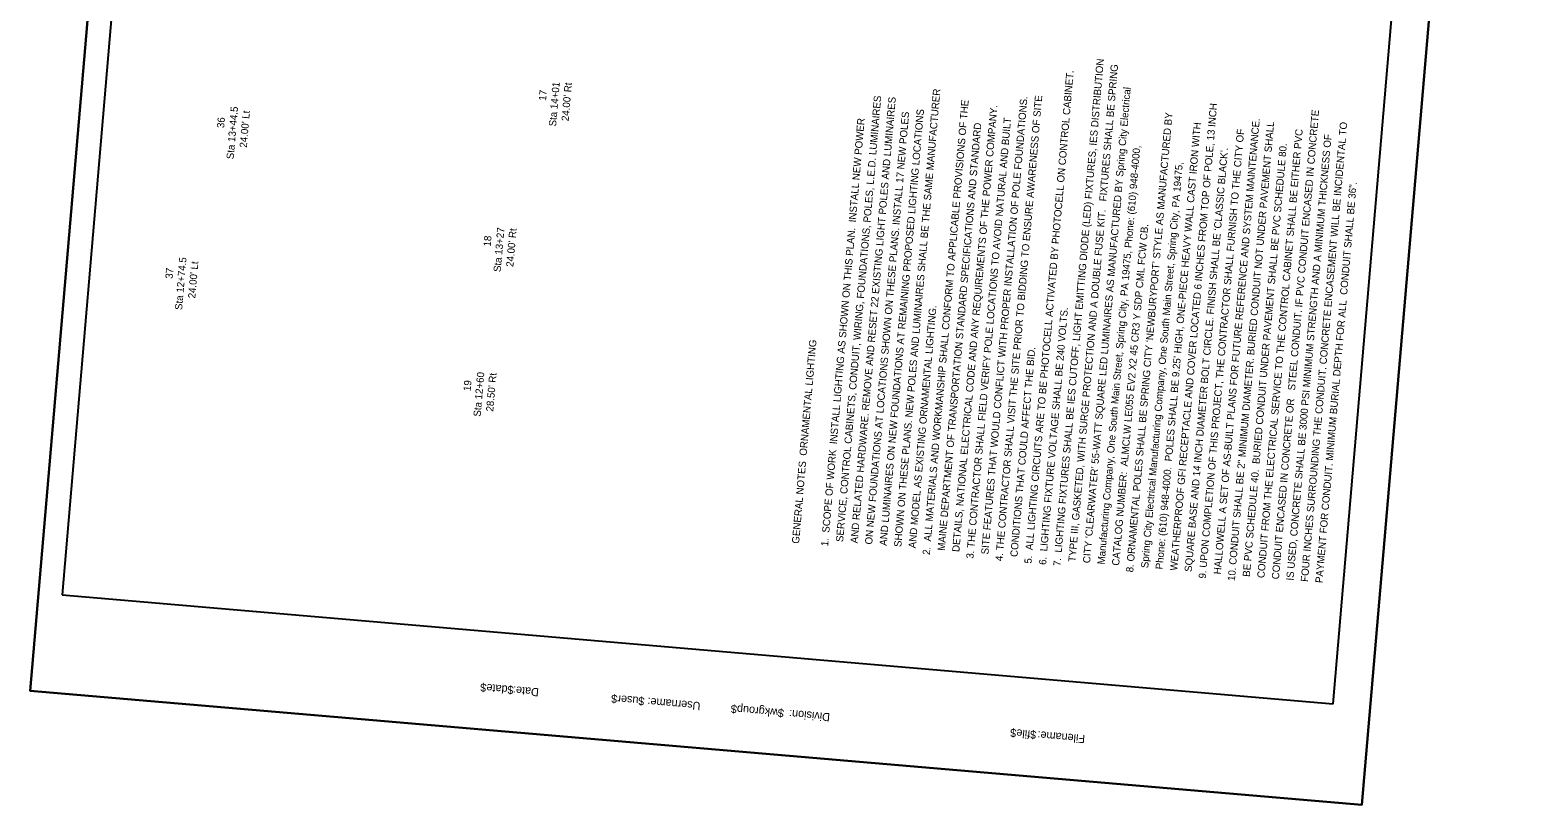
# Model space of a CAD drawing. Extents: x 1137099 to 1137719, y 529062 to 529956.
# Drawn here: x 1137099 to 1137719, y 529062 to 529381 of the extents above; entities that cross this region are included whole.
import ezdxf

# ---------------------------------------------------------------- set-up
doc = ezdxf.new("R2010")
doc.units = 0
for name, color, linetype in [('ANNOTATION', 7, 'Continuous'), ('BORDER', 7, 'Continuous'), ('D_Lighting_Text', 7, 'Continuous'), ('PLOT BOUNDARY', 7, 'Continuous')]:
    doc.layers.add(name, color=color, linetype=linetype)

msp = doc.modelspace()

# ---------------------------------------------------------------- linework, layer by layer
at = {"layer": 'ANNOTATION'}
msp.add_lwpolyline([(1137098.65, 529108.8), (1137171.14, 529955.71), (1137719.13, 529908.81), (1137646.65, 529061.9)], close=True, dxfattribs=at)
at = {"layer": 'BORDER'}
for p, q in [((1137179.99, 529945.38), (1137111.77, 529148.3)), ((1137634.86, 529103.53), (1137703.08, 529900.61)), ((1137111.77, 529148.3), (1137634.86, 529103.53))]:
    msp.add_line(p, q, dxfattribs=at)
at = {"layer": 'PLOT BOUNDARY'}
msp.add_lwpolyline([(1137646.65, 529061.9), (1137719.13, 529908.81), (1137171.14, 529955.71), (1137098.65, 529108.8)], close=True, dxfattribs=at)

# ---------------------------------------------------------------- texts
at = {"layer": 'ANNOTATION'}
for s, p in [('7.  LIGHTING FIXTURES SHALL BE IES CUTOFF, LIGHT EMITTING DIODE (LED) FIXTURES, IES DISTRIBUTION ', (1137522.7, 529160.05)), ('5.  ALL LIGHTING CIRCUITS ARE TO BE PHOTOCELL ACTIVATED BY PHOTOCELL ON CONTROL CABINET.', (1137510.75, 529161.07)), ('  TYPE III, GASKETED, WITH SURGE PROTECTION AND A DOUBLE FUSE KIT.   FIXTURES SHALL BE SPRING ', (1137528.68, 529159.54)), ('  SHOWN ON THESE PLANS. NEW POLES AND LUMINAIRES SHALL BE THE SAME MANUFACTURER ', (1137456.95, 529165.68)), ('  CITY ‘CLEARWATER’ 55-WATT SQUARE LED LUMINAIRES AS MANUFACTURED BY Spring City Electrical ', (1137534.66, 529159.02)), ('  SERVICE, CONTROL CABINETS, CONDUIT, WIRING, FOUNDATIONS, POLES, L.E.D. LUMINAIRES ', (1137433.03, 529167.72)), ('  AND RELATED HARDWARE. REMOVE AND RESET 22 EXISTING LIGHT POLES AND LUMINAIRES ', (1137439.01, 529167.21)), ('2.  ALL MATERIALS AND WORKMANSHIP SHALL CONFORM TO APPLICABLE PROVISIONS OF THE ', (1137468.9, 529164.65)), ('  DETAILS, NATIONAL ELECTRICAL CODE AND ANY REQUIREMENTS OF THE POWER COMPANY.', (1137480.86, 529163.63)), ('  SITE FEATURES THAT WOULD CONFLICT WITH PROPER INSTALLATION OF POLE FOUNDATIONS.', (1137492.81, 529162.61)), ('4. THE CONTRACTOR SHALL VISIT THE SITE PRIOR TO BIDDING TO ENSURE AWARENESS OF SITE ', (1137498.79, 529162.09)), ('  WEATHERPROOF GFI RECEPTACLE AND COVER LOCATED 6 INCHES FROM TOP OF POLE, 13 INCH ', (1137570.53, 529155.96)), ('1.  SCOPE OF WORK  INSTALL LIGHTING AS SHOWN ON THIS PLAN.  INSTALL NEW POWER ', (1137427.05, 529168.23)), ('  ON NEW FOUNDATIONS AT LOCATIONS SHOWN ON THESE PLANS. INSTALL 17 NEW POLES ', (1137444.99, 529166.7)), ('  AND LUMINAIRES ON NEW FOUNDATIONS AT REMAINING PROPOSED LIGHTING LOCATIONS ', (1137450.97, 529166.19)), ('3. THE CONTRACTOR SHALL FIELD VERIFY POLE LOCATIONS TO AVOID NATURAL AND BUILT ', (1137486.84, 529163.12)), ('8. ORNAMENTAL POLES SHALL BE SPRING CITY ‘NEWBURYPORT’ STYLE AS MANUFACTURED BY ', (1137552.6, 529157.49)), ('  Phone: (610) 948-4000.  POLES SHALL BE 9.25’ HIGH, ONE-PIECE HEAVY WALL CAST IRON WITH ', (1137564.55, 529156.47)), ('  HALLOWELL A SET OF AS-BUILT PLANS FOR FUTURE REFERENCE AND SYSTEM MAINTENANCE.', (1137588.46, 529154.42)), ('10. CONDUIT SHALL BE 2" MINIMUM DIAMETER. BURIED CONDUIT NOT UNDER PAVEMENT SHALL ', (1137594.44, 529153.91)), ('  CONDUIT ENCASED IN CONCRETE OR   STEEL CONDUIT. IF PVC CONDUIT ENCASED IN CONCRETE ', (1137612.38, 529152.37)), ('  FOUR INCHES SURROUNDING THE CONDUIT. CONCRETE ENCASEMENT WILL BE INCIDENTAL TO ', (1137624.33, 529151.35)), ('  MAINE DEPARTMENT OF TRANSPORTATION STANDARD SPECIFICATIONS AND STANDARD ', (1137474.88, 529164.14)), ('9. UPON COMPLETION OF THIS PROJECT, THE CONTRACTOR SHALL FURNISH TO THE CITY OF ', (1137582.49, 529154.93)), ('  CONDUIT FROM THE ELECTRICAL SERVICE TO THE CONTROL CABINET SHALL BE EITHER PVC ', (1137606.4, 529152.89)), ('  IS USED, CONCRETE SHALL BE 3000 PSI MINIMUM STRENGTH AND A MINIMUM THICKNESS OF ', (1137618.36, 529151.86)), ('  Manufacturing Company, One South Main Street, Spring City, PA 19475, Phone: (610) 948-4000, ', (1137540.64, 529158.51)), ('  SQUARE BASE AND 14 INCH DIAMETER BOLT CIRCLE. FINISH SHALL BE ‘CLASSIC BLACK’.', (1137576.51, 529155.44)), ('  BE PVC SCHEDULE 40.  BURIED CONDUIT UNDER PAVEMENT SHALL BE PVC SCHEDULE 80.  ', (1137600.42, 529153.4)), ('  Spring City Electrical Manufacturing Company, One South Main Street, Spring City, PA 19475, ', (1137558.57, 529156.98)), ('  PAYMENT FOR CONDUIT. MINIMUM BURIAL DEPTH FOR ALL  CONDUIT SHALL BE 36". ', (1137630.31, 529150.84)), ('  CATALOG NUMBER:  ALMCLW LE055 EV2 X2 45 CR3 Y SDP CML FCW CB.', (1137546.62, 529158)), ('  AND MODEL AS EXISTING ORNAMENTAL LIGHTING.', (1137462.92, 529165.16)), ('6.  LIGHTING FIXTURE VOLTAGE SHALL BE 240 VOLTS.', (1137516.73, 529160.56)), ('GENERAL NOTES  ORNAMENTAL LIGHTING', (1137415.1, 529169.26)), ('  CONDITIONS THAT COULD AFFECT THE BID.', (1137504.77, 529161.58))]:
    msp.add_text(s, height=3, rotation=85.10821, dxfattribs=at).set_placement(p)
at = {"layer": 'BORDER'}
for s, p in [('$date$', (1137297.72, 529110.73)), ('Date:', (1137308.13, 529109.84)), ('$user$', (1137351.59, 529106.12)), ('Username:', (1137374.63, 529104.15)), ('$wkgroup$', (1137408.99, 529101.2)), ('Division:', (1137427.94, 529099.58)), ('$file$', (1137512.83, 529092.32)), ('Filename:', (1137532.9, 529090.6))]:
    msp.add_text(s, height=3.348, rotation=175.10821, dxfattribs=at).set_placement(p)
at = {"layer": 'D_Lighting_Text'}
for s, p in [('17', (1137310.95, 529351.53)), ('Sta 14+01', (1137315.07, 529340.96)), ("24.00' Rt", (1137320.27, 529343.13)), ('Sta 13+44.5', (1137182.38, 529327.46)), ('36', (1137178.46, 529340.27)), ("24.00' Lt", (1137187.81, 529332.22)), ('Sta 13+27', (1137292.3, 529281.05)), ("24.00' Rt", (1137297.49, 529283.13)), ('18', (1137288.17, 529291.53)), ('Sta 12+74.5', (1137161.17, 529265.43)), ('37', (1137157.25, 529278.27)), ("24.00' Lt", (1137166.6, 529270.19)), ('Sta 12+60', (1137284.03, 529221.54)), ("28.50' Rt", (1137289.23, 529223.62)), ('19', (1137279.91, 529232.05))]:
    msp.add_text(s, height=3, rotation=85.10821, dxfattribs=at).set_placement(p)

doc.saveas('drawing.dxf')
